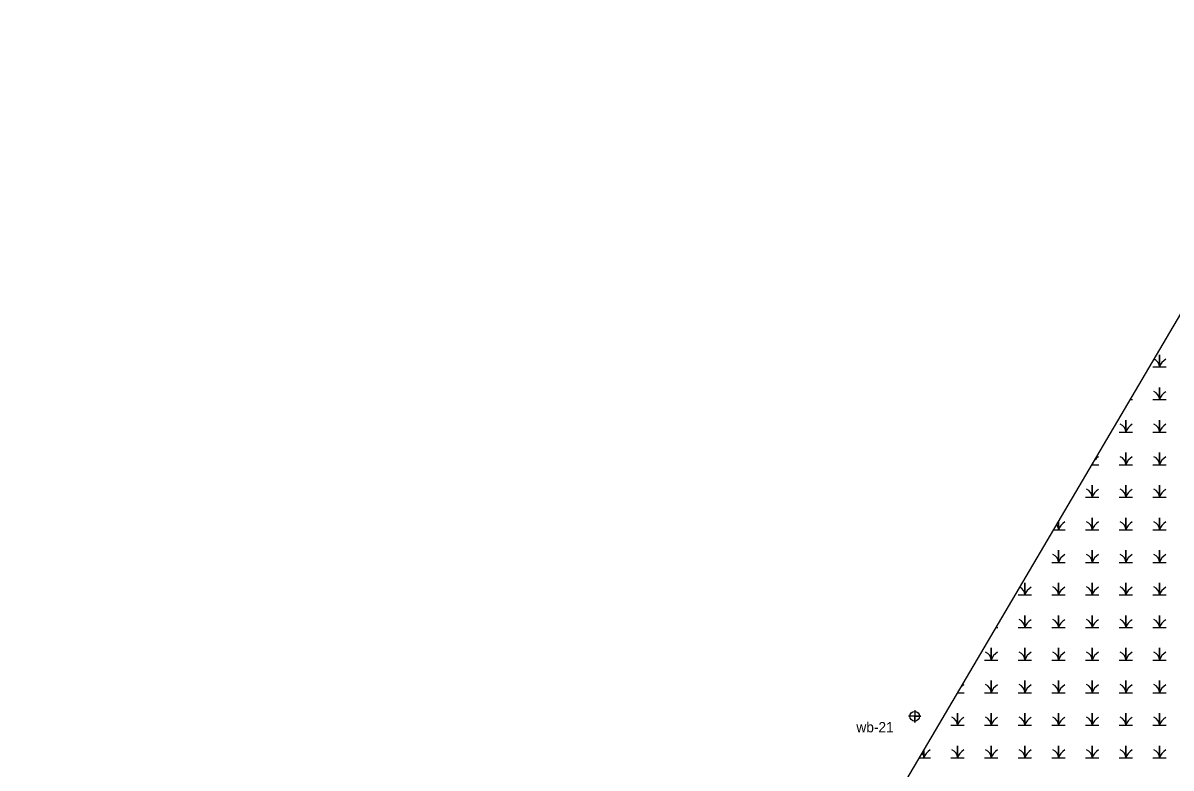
# Model space of a CAD drawing. Extents: x 2379288 to 2381905, y 330670 to 333511.
# Drawn here: x 2379288 to 2379849, y 331613 to 331977 of the extents above; entities that cross this region are included whole.
import ezdxf

# ---------------------------------------------------------------- set-up
doc = ezdxf.new("R2010")
doc.units = 0
for name, color, linetype in [('Default', 7, 'Continuous'), ('Exist Environmental Wetland Boundary Cogo Number', 7, 'Continuous'), ('Exist Environmental Wetland Boundary Cogo Point CELL', 7, 'Continuous'), ('Exist Hydro Swamp or Marsh', 7, 'Continuous')]:
    doc.layers.add(name, color=color, linetype=linetype)

msp = doc.modelspace()

# ---------------------------------------------------------------- linework, layer by layer
at = {"layer": 'Default'}
msp.add_lwpolyline([(2380453.94, 332065.55), (2379632.78, 330670.47), (2379288.07, 330873.37), (2380109.3, 332268.58)], dxfattribs=at)
at = {"layer": 'Exist Environmental Wetland Boundary Cogo Point CELL'}
msp.add_lwpolyline([(2379723.84, 331640.96), (2379723.84, 331634.96), (2379723.84, 331637.96), (2379726.84, 331637.96), (2379720.84, 331637.96)], dxfattribs=at)
msp.add_circle((2379723.84, 331637.96), 2.34, dxfattribs=at)
at = {"layer": 'Exist Hydro Swamp or Marsh'}
for p, q in [((2379829.22, 331792.75), (2379830.29, 331792.75)), ((2379763.64, 331681.33), (2379764.48, 331681.33)), ((2379744.9, 331649.49), (2379748.03, 331649.49))]:
    msp.add_line(p, q, dxfattribs=at)
for points in [[(2379840.29, 331808.67), (2379843.51, 331808.67), (2379843.51, 331814.59), (2379843.51, 331808.67), (2379846.74, 331808.67)], [(2379840.29, 331792.75), (2379843.51, 331792.75), (2379843.51, 331798.67), (2379843.51, 331792.75), (2379846.74, 331792.75)], [(2379823.84, 331776.83), (2379827.06, 331776.83), (2379827.06, 331782.75), (2379827.06, 331776.83), (2379830.29, 331776.83)], [(2379840.29, 331776.83), (2379843.51, 331776.83), (2379843.51, 331782.75), (2379843.51, 331776.83), (2379846.74, 331776.83)], [(2379823.84, 331760.92), (2379827.06, 331760.92), (2379827.06, 331766.83), (2379827.06, 331760.92), (2379830.29, 331760.92)], [(2379840.29, 331760.92), (2379843.51, 331760.92), (2379843.51, 331766.83), (2379843.51, 331760.92), (2379846.74, 331760.92)], [(2379810.48, 331760.92), (2379810.61, 331760.92), (2379810.61, 331761.13)], [(2379810.61, 331761.13), (2379810.61, 331760.92), (2379813.84, 331760.92)], [(2379807.39, 331745), (2379810.61, 331745), (2379810.61, 331750.92), (2379810.61, 331745), (2379813.84, 331745)], [(2379823.84, 331745), (2379827.06, 331745), (2379827.06, 331750.92), (2379827.06, 331745), (2379830.29, 331745)], [(2379840.29, 331745), (2379843.51, 331745), (2379843.51, 331750.92), (2379843.51, 331745), (2379846.74, 331745)], [(2379791.74, 331729.08), (2379794.16, 331729.08), (2379794.16, 331733.18)], [(2379794.16, 331733.18), (2379794.16, 331729.08), (2379797.39, 331729.08)], [(2379807.39, 331729.08), (2379810.61, 331729.08), (2379810.61, 331735), (2379810.61, 331729.08), (2379813.84, 331729.08)], [(2379823.84, 331729.08), (2379827.06, 331729.08), (2379827.06, 331735), (2379827.06, 331729.08), (2379830.29, 331729.08)], [(2379840.29, 331729.08), (2379843.51, 331729.08), (2379843.51, 331735), (2379843.51, 331729.08), (2379846.74, 331729.08)], [(2379790.93, 331713.16), (2379794.16, 331713.16), (2379794.16, 331719.08), (2379794.16, 331713.16), (2379797.39, 331713.16)], [(2379807.39, 331713.16), (2379810.61, 331713.16), (2379810.61, 331719.08), (2379810.61, 331713.16), (2379813.84, 331713.16)], [(2379823.84, 331713.16), (2379827.06, 331713.16), (2379827.06, 331719.08), (2379827.06, 331713.16), (2379830.29, 331713.16)], [(2379840.29, 331713.16), (2379843.51, 331713.16), (2379843.51, 331719.08), (2379843.51, 331713.16), (2379846.74, 331713.16)], [(2379774.48, 331697.25), (2379777.71, 331697.25), (2379777.71, 331703.16), (2379777.71, 331697.25), (2379780.93, 331697.25)], [(2379790.93, 331697.25), (2379794.16, 331697.25), (2379794.16, 331703.16), (2379794.16, 331697.25), (2379797.39, 331697.25)], [(2379807.39, 331697.25), (2379810.61, 331697.25), (2379810.61, 331703.16), (2379810.61, 331697.25), (2379813.84, 331697.25)], [(2379823.84, 331697.25), (2379827.06, 331697.25), (2379827.06, 331703.16), (2379827.06, 331697.25), (2379830.29, 331697.25)], [(2379840.29, 331697.25), (2379843.51, 331697.25), (2379843.51, 331703.16), (2379843.51, 331697.25), (2379846.74, 331697.25)], [(2379774.48, 331681.33), (2379777.71, 331681.33), (2379777.71, 331687.25), (2379777.71, 331681.33), (2379780.93, 331681.33)], [(2379790.93, 331681.33), (2379794.16, 331681.33), (2379794.16, 331687.25), (2379794.16, 331681.33), (2379797.39, 331681.33)], [(2379807.39, 331681.33), (2379810.61, 331681.33), (2379810.61, 331687.25), (2379810.61, 331681.33), (2379813.84, 331681.33)], [(2379823.84, 331681.33), (2379827.06, 331681.33), (2379827.06, 331687.25), (2379827.06, 331681.33), (2379830.29, 331681.33)], [(2379840.29, 331681.33), (2379843.51, 331681.33), (2379843.51, 331687.25), (2379843.51, 331681.33), (2379846.74, 331681.33)], [(2379758.03, 331665.41), (2379761.26, 331665.41), (2379761.26, 331671.33), (2379761.26, 331665.41), (2379764.48, 331665.41)], [(2379774.48, 331665.41), (2379777.71, 331665.41), (2379777.71, 331671.33), (2379777.71, 331665.41), (2379780.93, 331665.41)], [(2379790.93, 331665.41), (2379794.16, 331665.41), (2379794.16, 331671.33), (2379794.16, 331665.41), (2379797.39, 331665.41)], [(2379807.39, 331665.41), (2379810.61, 331665.41), (2379810.61, 331671.33), (2379810.61, 331665.41), (2379813.84, 331665.41)], [(2379823.84, 331665.41), (2379827.06, 331665.41), (2379827.06, 331671.33), (2379827.06, 331665.41), (2379830.29, 331665.41)], [(2379840.29, 331665.41), (2379843.51, 331665.41), (2379843.51, 331671.33), (2379843.51, 331665.41), (2379846.74, 331665.41)], [(2379758.03, 331649.49), (2379761.26, 331649.49), (2379761.26, 331655.41), (2379761.26, 331649.49), (2379764.48, 331649.49)], [(2379774.48, 331649.49), (2379777.71, 331649.49), (2379777.71, 331655.41), (2379777.71, 331649.49), (2379780.93, 331649.49)], [(2379790.93, 331649.49), (2379794.16, 331649.49), (2379794.16, 331655.41), (2379794.16, 331649.49), (2379797.39, 331649.49)], [(2379807.39, 331649.49), (2379810.61, 331649.49), (2379810.61, 331655.41), (2379810.61, 331649.49), (2379813.84, 331649.49)], [(2379823.84, 331649.49), (2379827.06, 331649.49), (2379827.06, 331655.41), (2379827.06, 331649.49), (2379830.29, 331649.49)], [(2379840.29, 331649.49), (2379843.51, 331649.49), (2379843.51, 331655.41), (2379843.51, 331649.49), (2379846.74, 331649.49)], [(2379741.58, 331633.58), (2379744.81, 331633.58), (2379744.81, 331639.49), (2379744.81, 331633.58), (2379748.03, 331633.58)], [(2379758.03, 331633.58), (2379761.26, 331633.58), (2379761.26, 331639.49), (2379761.26, 331633.58), (2379764.48, 331633.58)], [(2379774.48, 331633.58), (2379777.71, 331633.58), (2379777.71, 331639.49), (2379777.71, 331633.58), (2379780.93, 331633.58)], [(2379790.93, 331633.58), (2379794.16, 331633.58), (2379794.16, 331639.49), (2379794.16, 331633.58), (2379797.39, 331633.58)], [(2379807.39, 331633.58), (2379810.61, 331633.58), (2379810.61, 331639.49), (2379810.61, 331633.58), (2379813.84, 331633.58)], [(2379823.84, 331633.58), (2379827.06, 331633.58), (2379827.06, 331639.49), (2379827.06, 331633.58), (2379830.29, 331633.58)], [(2379840.29, 331633.58), (2379843.51, 331633.58), (2379843.51, 331639.49), (2379843.51, 331633.58), (2379846.74, 331633.58)], [(2379726.16, 331617.66), (2379728.35, 331617.66), (2379728.35, 331621.39)], [(2379728.35, 331621.39), (2379728.35, 331617.66), (2379731.58, 331617.66)], [(2379741.58, 331617.66), (2379744.81, 331617.66), (2379744.81, 331623.58), (2379744.81, 331617.66), (2379748.03, 331617.66)], [(2379758.03, 331617.66), (2379761.26, 331617.66), (2379761.26, 331623.58), (2379761.26, 331617.66), (2379764.48, 331617.66)], [(2379774.48, 331617.66), (2379777.71, 331617.66), (2379777.71, 331623.58), (2379777.71, 331617.66), (2379780.93, 331617.66)], [(2379790.93, 331617.66), (2379794.16, 331617.66), (2379794.16, 331623.58), (2379794.16, 331617.66), (2379797.39, 331617.66)], [(2379807.39, 331617.66), (2379810.61, 331617.66), (2379810.61, 331623.58), (2379810.61, 331617.66), (2379813.84, 331617.66)], [(2379823.84, 331617.66), (2379827.06, 331617.66), (2379827.06, 331623.58), (2379827.06, 331617.66), (2379830.29, 331617.66)], [(2379840.29, 331617.66), (2379843.51, 331617.66), (2379843.51, 331623.58), (2379843.51, 331617.66), (2379846.74, 331617.66)]]:
    msp.add_lwpolyline(points, dxfattribs=at)
for centre, radius, start, end in [((2379838.91, 331808.34), 4.61, 4.1403, 65.0781), ((2379850.35, 331806.4), 7.21, 122.1274, 161.6222), ((2379838.91, 331792.42), 4.61, 4.1403, 67.535), ((2379850.35, 331790.48), 7.21, 122.1274, 161.6222), ((2379822.46, 331776.5), 4.61, 4.1403, 67.535), ((2379833.9, 331774.56), 7.21, 122.1274, 161.6222), ((2379838.91, 331776.5), 4.61, 4.1403, 67.535), ((2379850.35, 331774.56), 7.21, 122.1274, 161.6222), ((2379806.01, 331760.58), 4.61, 4.1403, 6.478), ((2379817.45, 331758.64), 7.21, 156.285, 161.6222), ((2379817.45, 331758.64), 7.21, 122.1274, 142.7523), ((2379822.46, 331760.58), 4.61, 4.1403, 67.535), ((2379833.9, 331758.64), 7.21, 122.1274, 161.6222), ((2379838.91, 331760.58), 4.61, 4.1403, 67.535), ((2379850.35, 331758.64), 7.21, 122.1274, 161.6222), ((2379806.01, 331744.67), 4.61, 4.1403, 67.535), ((2379817.45, 331742.73), 7.21, 122.1274, 161.6222), ((2379822.46, 331744.67), 4.61, 4.1403, 67.535), ((2379833.9, 331742.73), 7.21, 122.1274, 161.6222), ((2379838.91, 331744.67), 4.61, 4.1403, 67.535), ((2379850.35, 331742.73), 7.21, 122.1274, 161.6222), ((2379789.56, 331728.75), 4.61, 4.1403, 37.7014), ((2379801, 331726.81), 7.21, 122.1274, 161.6222), ((2379806.01, 331728.75), 4.61, 4.1403, 67.535), ((2379817.45, 331726.81), 7.21, 122.1274, 161.6222), ((2379822.46, 331728.75), 4.61, 4.1403, 67.535), ((2379833.9, 331726.81), 7.21, 122.1274, 161.6222), ((2379838.91, 331728.75), 4.61, 4.1403, 67.535), ((2379850.35, 331726.81), 7.21, 122.1274, 161.6222), ((2379789.56, 331712.83), 4.61, 4.1403, 67.535), ((2379801, 331710.89), 7.21, 122.1274, 161.6222), ((2379806.01, 331712.83), 4.61, 4.1403, 67.535), ((2379817.45, 331710.89), 7.21, 122.1274, 161.6222), ((2379822.46, 331712.83), 4.61, 4.1403, 67.535), ((2379833.9, 331710.89), 7.21, 122.1274, 161.6222), ((2379838.91, 331712.83), 4.61, 4.1403, 67.535), ((2379850.35, 331710.89), 7.21, 122.1274, 161.6222), ((2379773.11, 331696.91), 4.61, 4.1403, 62.7155), ((2379784.55, 331694.97), 7.21, 122.1274, 161.6222), ((2379789.56, 331696.91), 4.61, 4.1403, 67.535), ((2379801, 331694.97), 7.21, 122.1274, 161.6222), ((2379806.01, 331696.91), 4.61, 4.1403, 67.535), ((2379817.45, 331694.97), 7.21, 122.1274, 161.6222), ((2379822.46, 331696.91), 4.61, 4.1403, 67.535), ((2379833.9, 331694.97), 7.21, 122.1274, 161.6222), ((2379838.91, 331696.91), 4.61, 4.1403, 67.535), ((2379850.35, 331694.97), 7.21, 122.1274, 161.6222), ((2379773.11, 331681), 4.61, 4.1403, 67.535), ((2379784.55, 331679.06), 7.21, 122.1274, 161.6222), ((2379789.56, 331681), 4.61, 4.1403, 67.535), ((2379801, 331679.06), 7.21, 122.1274, 161.6222), ((2379806.01, 331681), 4.61, 4.1403, 67.535), ((2379817.45, 331679.06), 7.21, 122.1274, 161.6222), ((2379822.46, 331681), 4.61, 4.1403, 67.535), ((2379833.9, 331679.06), 7.21, 122.1274, 161.6222), ((2379838.91, 331681), 4.61, 4.1403, 67.535), ((2379850.35, 331679.06), 7.21, 122.1274, 161.6222), ((2379756.66, 331665.08), 4.61, 4.1403, 67.535), ((2379768.1, 331663.14), 7.21, 122.1274, 161.6222), ((2379773.11, 331665.08), 4.61, 4.1403, 67.535), ((2379784.55, 331663.14), 7.21, 122.1274, 161.6222), ((2379789.56, 331665.08), 4.61, 4.1403, 67.535), ((2379801, 331663.14), 7.21, 122.1274, 161.6222), ((2379806.01, 331665.08), 4.61, 4.1403, 67.535), ((2379817.45, 331663.14), 7.21, 122.1274, 161.6222), ((2379822.46, 331665.08), 4.61, 4.1403, 67.535), ((2379833.9, 331663.14), 7.21, 122.1274, 161.6222), ((2379838.91, 331665.08), 4.61, 4.1403, 67.535), ((2379850.35, 331663.14), 7.21, 122.1274, 161.6222), ((2379751.65, 331647.22), 7.21, 122.1274, 134.6981), ((2379756.66, 331649.16), 4.61, 4.1403, 67.535), ((2379768.1, 331647.22), 7.21, 122.1274, 161.6222), ((2379773.11, 331649.16), 4.61, 4.1403, 67.535), ((2379784.55, 331647.22), 7.21, 122.1274, 161.6222), ((2379789.56, 331649.16), 4.61, 4.1403, 67.535), ((2379801, 331647.22), 7.21, 122.1274, 161.6222), ((2379806.01, 331649.16), 4.61, 4.1403, 67.535), ((2379817.45, 331647.22), 7.21, 122.1274, 161.6222), ((2379822.46, 331649.16), 4.61, 4.1403, 67.535), ((2379833.9, 331647.22), 7.21, 122.1274, 161.6222), ((2379838.91, 331649.16), 4.61, 4.1403, 67.535), ((2379850.35, 331647.22), 7.21, 122.1274, 161.6222), ((2379740.21, 331633.24), 4.61, 4.1403, 67.535), ((2379751.65, 331631.3), 7.21, 122.1274, 161.6222), ((2379756.66, 331633.24), 4.61, 4.1403, 67.535), ((2379768.1, 331631.3), 7.21, 122.1274, 161.6222), ((2379773.11, 331633.24), 4.61, 4.1403, 67.535), ((2379784.55, 331631.3), 7.21, 122.1274, 161.6222), ((2379789.56, 331633.24), 4.61, 4.1403, 67.535), ((2379801, 331631.3), 7.21, 122.1274, 161.6222), ((2379806.01, 331633.24), 4.61, 4.1403, 67.535), ((2379817.45, 331631.3), 7.21, 122.1274, 161.6222), ((2379822.46, 331633.24), 4.61, 4.1403, 67.535), ((2379833.9, 331631.3), 7.21, 122.1274, 161.6222), ((2379838.91, 331633.24), 4.61, 4.1403, 67.535), ((2379850.35, 331631.3), 7.21, 122.1274, 161.6222), ((2379723.75, 331617.32), 4.61, 4.1403, 35.1403), ((2379735.2, 331615.38), 7.21, 122.1274, 161.6222), ((2379740.21, 331617.32), 4.61, 4.1403, 67.535), ((2379751.65, 331615.38), 7.21, 122.1274, 161.6222), ((2379756.66, 331617.32), 4.61, 4.1403, 67.535), ((2379768.1, 331615.38), 7.21, 122.1274, 161.6222), ((2379773.11, 331617.32), 4.61, 4.1403, 67.535), ((2379784.55, 331615.38), 7.21, 122.1274, 161.6222), ((2379789.56, 331617.32), 4.61, 4.1403, 67.535), ((2379801, 331615.38), 7.21, 122.1274, 161.6222), ((2379806.01, 331617.32), 4.61, 4.1403, 67.535), ((2379817.45, 331615.38), 7.21, 122.1274, 161.6222), ((2379822.46, 331617.32), 4.61, 4.1403, 67.535), ((2379833.9, 331615.38), 7.21, 122.1274, 161.6222), ((2379838.91, 331617.32), 4.61, 4.1403, 67.535), ((2379850.35, 331615.38), 7.21, 122.1274, 161.6222)]:
    msp.add_arc(centre, radius, start, end, dxfattribs=at)

# ---------------------------------------------------------------- texts
at = {"layer": 'Exist Environmental Wetland Boundary Cogo Number'}
msp.add_text('wb-21', height=5, dxfattribs=at).set_placement((2379695.36, 331630.12))

doc.saveas('drawing.dxf')
